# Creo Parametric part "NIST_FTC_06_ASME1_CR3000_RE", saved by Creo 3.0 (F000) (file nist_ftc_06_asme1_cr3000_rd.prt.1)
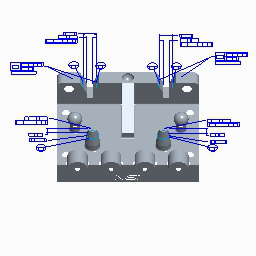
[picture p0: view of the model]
Units: Inch lbm Second (Pro/E Default); INCH, POUND, SECS

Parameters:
  PART_NUMBER = "NIST PMI FTC 06 ASME1"
  REVISION = "D"
  DESCRIPTION = "NIST PMI test model downloaded from http://go.usa.gov/mGVm"

Created from: NIST_FTC_06_ASME1_CR3000_RD.PRT

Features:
  1. datum plane "RIGHT"
  2. datum plane "TOP"
  3. datum plane "FRONT"
  4. coordinate system
  5. curve
  6. protrusion
  7. curve
  8. datum plane "DTM1"
  9. pattern
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
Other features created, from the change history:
  sketch "Sketch 17"
  extruded cut "Extrude 7"
  annotation "Annotation 43"

Other named items: ABC, DBC, F1, F2, F3, F4, EAB, DCK, DCJ, DG, DH, A, B, C, D, E, J, K, F, G, H, AE_GTOL0, AE_SET_DATUM_TAG_A, AE_DRIVEN_DIM0, AE_GTOL1, AE_SET_DATUM_TAG_B, AE_GTOL2, AE_SET_DATUM_TAG_C, AE_GTOL3, AE_GTOL4, AE_SET_DATUM_TAG_D, AE_GTOL5, AE_GTOL6, AE_SET_DATUM_TAG_E, AE_DRIVEN_DIM1, AE_GTOL7, AE_SET_DATUM_TAG_F, AE_DRIVEN_DIM2, AE_GTOL8, AE_DRIVEN_DIM3, AE_DRIVEN_DIM4, AE_GTOL9, AE_DRIVEN_DIM5, AE_GTOL10, AE_DRIVEN_DIM6, AE_GTOL11, AE_DRIVEN_DIM7, AE_GTOL13, AE_GTOL14, AE_GTOL15, AE_NOTE0, AE_NOTE1, AE_DRIVEN_DIM10, AE_SET_DATUM_TAG_J, AE_DTM_TARGET_J_1, AE_DTM_TARGET_J_2, AE_GTOL17, AE_GTOL18, AE_SET_DATUM_TAG_K, AE_DTM_TARGET_K_1, AE_DTM_TARGET_K_2, AE_DRIVEN_DIM12, AE_GTOL20, AE_GTOL21, AE_DRIVEN_DIM14, AE_SET_DATUM_TAG_G, AE_DTM_TARGET_G_1, AE_SET_DATUM_TAG_H, AE_DTM_TARGET_H_1, AE_GTOL24, AE_DRIVEN_DIM18, AE_GTOL25, AE_NOTE2, AE_DRIVEN_DIM22, AE_DRIVEN_DIM23, AE_DRIVEN_DIM24, AE_GTOL30, AE_GTOL31, AE_DRIVEN_DIM25, AE_DRIVEN_DIM26, AE_DRIVEN_DIM27, AE_DRIVEN_DIM28, AE_DRIVEN_DIM29, AE_NOTE3, AE_REFERENCE_DIM0, AE_REFERENCE_DIM1, AE_REFERENCE_DIM2, AE_REFERENCE_DIM3, REP0001, MBD_A, MBD_B, MBD_C, LAYER_STATE001, ANNOT_LAYER_STATE0001, LAYER_STATE002, ANNOT_LAYER_STATE0002, LAYER_STATE003, LAYER_STATE004, ANNOT_LAYER_STATE0003, LAYER_STATE005

Family table entries: GENERIC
